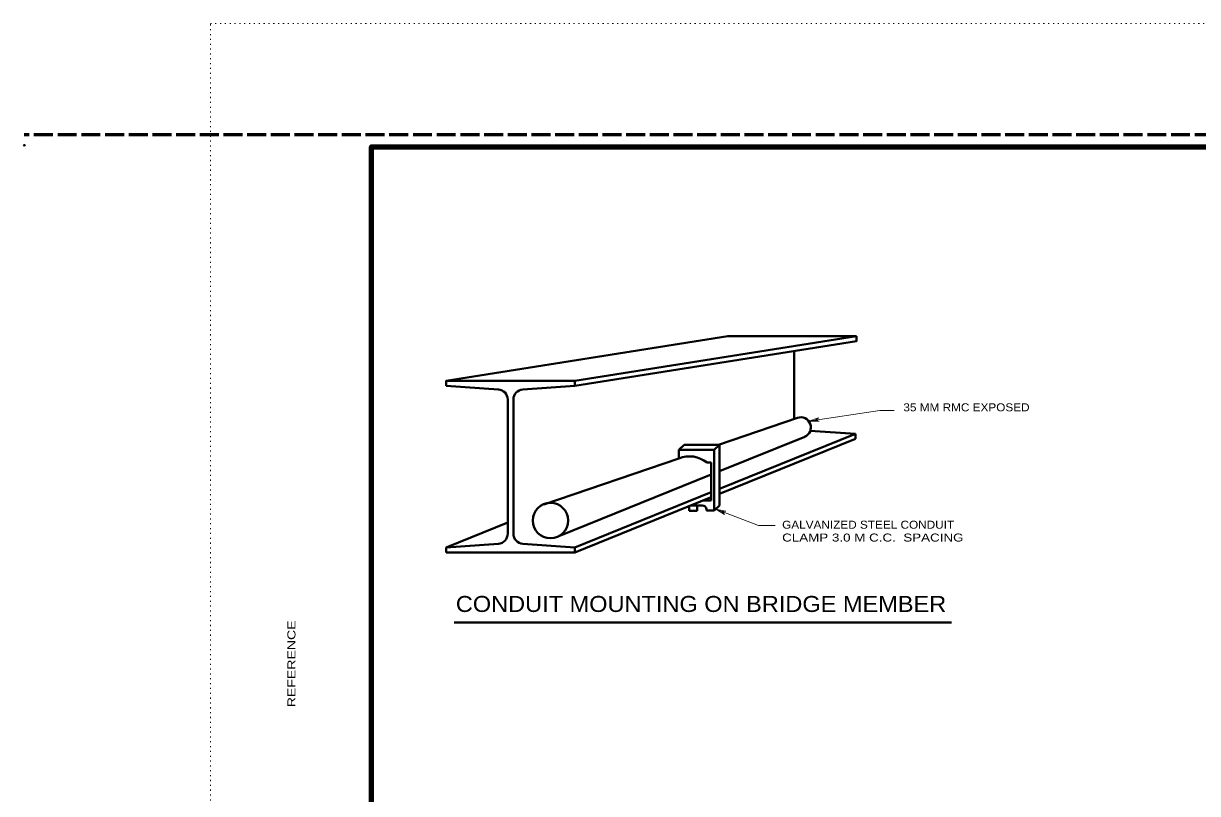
# Model space of a CAD drawing. Extents: x 312583 to 312854, y 144419 to 144597.
# Drawn here: x 312583.5 to 312695, y 144523.7 to 144596.8 of the extents above; entities that cross this region are included whole.
import ezdxf
from ezdxf.enums import TextEntityAlignment as Align

# ---------------------------------------------------------------- set-up
doc = ezdxf.new("R2010")
doc.units = 0
doc.header["$LTSCALE"] = 0.3
doc.header["$PDMODE"] = 32
doc.header["$PDSIZE"] = 0.15
doc.linetypes.add('DOTTED', pattern=[1.5, 0.3, -1.2])
doc.linetypes.add('LONG_DASHED', pattern=[7.5, 6, -1.5])
for name, color, linetype, lineweight in [('1', 7, 'Continuous', 40), ('2', 7, 'Continuous', 13), ('62', 7, 'DOTTED', 13), ('63', 7, 'LONG_DASHED', 60)]:
    doc.layers.add(name, color=color, linetype=linetype, lineweight=lineweight)
doc.layers.add('39', color=7, linetype='Continuous')

msp = doc.modelspace()

# ---------------------------------------------------------------- linework, layer by layer
at = {"layer": '1'}
for p, q in [((312656.6395, 144559.217), (312656.6395, 144565.6723)), ((312623.6038, 144562.851), (312635.8245, 144562.851)), ((312623.6038, 144562.3757), (312628.5565, 144562.0307)), ((312635.8245, 144562.3757), (312630.8718, 144562.0307)), ((312629.4458, 144548.338), (312629.4458, 144561.0723)), ((312629.9825, 144548.338), (312629.9825, 144561.0723)), ((312649.4635, 144556.7637), (312656.9692, 144559.332)), ((312649.5478, 144552.5777), (312662.4815, 144557.8063)), ((312649.5478, 144554.2643), (312657.6515, 144557.538)), ((312649.5478, 144552.11), (312662.4815, 144557.331)), ((312662.4815, 144557.8063), (312658.1882, 144558.1053)), ((312662.4815, 144557.331), (312662.4815, 144557.8063)), ((312645.7145, 144556.2807), (312646.1975, 144556.7637)), ((312645.7145, 144556.2807), (312645.7145, 144555.4833)), ((312649.0648, 144556.2807), (312649.5478, 144556.7637)), ((312632.8882, 144551.0903), (312645.7145, 144555.4833)), ((312648.3748, 144555.0847), (312648.7582, 144555.0847)), ((312648.7582, 144555.0847), (312648.7582, 144551.489)), ((312634.2988, 144548.1003), (312648.7582, 144553.9423)), ((312635.8245, 144547.0347), (312648.7582, 144552.2633)), ((312635.8245, 144546.5593), (312648.7582, 144551.788)), ((312646.6805, 144550.5077), (312646.6805, 144550.9447)), ((312646.6805, 144550.5077), (312647.4472, 144550.5077)), ((312646.8492, 144551.0137), (312647.9302, 144551.0137)), ((312647.4472, 144550.5077), (312647.4472, 144550.983)), ((312648.0222, 144551.489), (312648.7582, 144551.489)), ((312648.3135, 144550.6303), (312648.3135, 144550.5307)), ((312648.3135, 144550.5307), (312649.0648, 144550.5307)), ((312649.0648, 144550.5307), (312649.5478, 144551.0137)), ((312623.6038, 144547.0347), (312629.4458, 144549.396)), ((312623.6038, 144547.0347), (312628.5565, 144547.3797)), ((312635.8245, 144547.0347), (312630.8718, 144547.3797)), ((312623.6038, 144546.5593), (312623.6038, 144547.0347)), ((312623.6038, 144546.5593), (312635.8245, 144546.5593)), ((312635.8245, 144546.5593), (312635.8245, 144547.0347))]:
    msp.add_line(p, q, dxfattribs=at)
at = {"layer": '1', "lineweight": 158}
msp.add_lwpolyline([(312616.5, 144423.1446), (312616.5, 144585.0846), (312849, 144585.0846)], dxfattribs=at)
at = {"layer": '1'}
for points in [[(312623.6038, 144562.3757), (312623.6038, 144562.851), (312650.3452, 144567.0907), (312662.5658, 144567.0907)], [(312635.8245, 144562.3757), (312635.8245, 144562.851), (312662.5658, 144567.0907)], [(312635.8245, 144562.3757), (312662.5658, 144566.6153), (312662.5658, 144567.0907)], [(312645.7145, 144556.2807), (312649.0648, 144556.2807), (312649.0648, 144550.5307)], [(312646.1975, 144556.7637), (312649.5478, 144556.7637), (312649.5478, 144551.0137)]]:
    msp.add_lwpolyline(points, dxfattribs=at)
msp.add_circle((312633.5092, 144549.58), 1.679, dxfattribs=at)
for centre, radius, start, end in [((312628.4875, 144561.0717), 0.9583, 0, 85.97943), ((312630.9408, 144561.0717), 0.9583, 94.02057, 180), ((312657.2835, 144558.4273), 0.9583, 292.47943, 109.16017), ((312646.7106, 144553.0431), 2.6357, 50.81442, 112.20624), ((312647.9302, 144550.6303), 0.3833, 0, 90), ((312628.4875, 144548.3383), 0.9583, 274.01723, 0), ((312630.9408, 144548.3383), 0.9583, 180.02006, 265.88325)]:
    msp.add_arc(centre, radius, start, end, dxfattribs=at)
at = {"layer": '2'}
msp.add_line((312666.1385, 144560.0373), (312664.7892, 144560.0373), dxfattribs=at)
at = {"layer": '2', "lineweight": 40}
msp.add_line((312624.3739, 144539.9047), (312671.5963, 144539.9047), dxfattribs=at)
at = {"layer": '2'}
for points in [[(312664.7892, 144560.0373), (312658.0348, 144559.0253), (312659.0162, 144559.01), (312658.6712, 144559.1173), (312658.9625, 144559.3243), (312658.0348, 144559.0253)], [(312654.8378, 144549.1123), (312653.2662, 144549.1123), (312649.2028, 144550.6687)]]:
    msp.add_lwpolyline(points, dxfattribs=at)
msp.add_lwpolyline([(312649.2028, 144550.6687), (312650.0462, 144550.1703), (312649.8008, 144550.4387), (312650.1612, 144550.477)], close=True, dxfattribs=at)
at = {"layer": '39'}
msp.add_point((312583.526, 144585.2246), dxfattribs=at)
at = {"layer": '62'}
for p, q in [((312601.2, 144596.7846), (312853.5, 144596.7846)), ((312601.2, 144418.5846), (312601.2, 144596.7846))]:
    msp.add_line(p, q, dxfattribs=at)
at = {"layer": '63'}
msp.add_line((312851.75, 144586.2246), (312583.526, 144586.2246), dxfattribs=at)

# ---------------------------------------------------------------- texts
at = {"layer": '1', "width": 1.3}
msp.add_text('REFERENCE                                                              ', height=0.7682, rotation=90, dxfattribs=at).set_placement((312609.2854, 144531.8549))
at = {"layer": '2'}
for s, width, p in [('35 MM RMC EXPOSED', 1.1, (312667.0278, 144559.952)), ('GALVANIZED STEEL CONDUIT', 1.1, (312655.5125, 144548.8047)), ('CLAMP 3.0 M C.C.  SPACING', 1.25, (312655.5125, 144547.5847))]:
    msp.add_text(s, height=0.76, dxfattribs=dict(at, width=width)).set_placement(p)
at = {"layer": '2', "width": 1.1}
msp.add_text('CONDUIT MOUNTING ON BRIDGE MEMBER', height=1.52, dxfattribs=at).set_placement((312647.8078, 144540.899), align=Align.CENTER)

doc.saveas('drawing.dxf')
